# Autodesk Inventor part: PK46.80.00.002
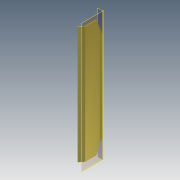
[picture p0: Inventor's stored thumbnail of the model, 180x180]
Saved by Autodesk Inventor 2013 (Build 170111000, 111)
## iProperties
Shininess: 64.0
Length Units: 11269
Angle Units: 11279
Time Units: 11290
Mass Units: 11283
Length Display Precision: 3
Angle Display Precision: 2
Compacted: True
Part Number: PK46.80.00.002
Document SubType Name: Sheet Metal
Created: 2004-12
Material: Steel, Mild
Designer: Salex
Manufacturer: Standard
Standards Organization: Custom
Density: 7.86 g/cm^3
Sheet Metal Rule: Default
Mass: 75176.4 g
Surface Area: 24385.2 cm^2
Volume: 9564.43 cm^3
Density: 0.0
Volumn: 0.0
Area: 0.0
PropertySet Name: Model Information
Control State: 0
Master: False
Checked Out: False
Checked Out Date: 2008-10-15
Last Check In Date: 2008-10-15
Author: Salex
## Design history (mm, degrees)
node "Contour Flange1"
  sketch "Sketch1"
    geometry: L1 (0, 0)-(0, 360); L2 (0, 0)-(-70, -90)
    constraints: 4 end point, 1 vertical, 1 other
    dimensions: "d16" = 70 horizontal distance of L1.start L2.end; "d19" = 360 distance of L1.start L1.end; "d23" = 90 vertical distance of L1.start L2.end
feature "Угловая фаска3" dims "d25" = 300, "d26" = 115, angle "d27" = 45 deg
feature "Угловая фаска4" dims "d28" = 300 (= d25), "d29" = 115 (= d26), angle "d30" = 45 deg
node "РабОсь1"
feature "Сгиб по линии1" dims "d32" = 8 (= BendReliefWidth), "d33" = 4 (= BendReliefDepth), "d34" = 16 (= MinimumRemnant), "d35" = 10 (= BendRadius), "d36" = 50 deg, "d37" = 10 (= BendRadius), "SeamGap" = 0.01, "Thickness" = 8
node "РабПлоскость1"
node "РабПлоскость2"
body "Solid1"
sketch "Эскиз3"
  geometry: L1 (2280, 356.569)-(2580, 241.569) reference; L2 (2280, 356.569)-(300, 356.569) reference; L3 (0, 241.569)-(300, 356.569) reference; L4 (195.652, 316.569)-(2384.348, 316.569)
  constraints: 2 end point, 2 point on line, 1 parallel
  dimensions: "d31" = 40 distance between parallel lines of L2 L4
face "Plate1" dims "d3" = 2580, "d4" = 8 (= BendReliefWidth), "d6" = 16 (= MinimumRemnant), "d8" = 10 (= BendRadius), "d9" = 8, "Thickness" = 8
bend "Bend1" dims "d4" = 8 (= BendReliefWidth), "d5" = 4 (= BendReliefDepth), "d6" = 16 (= MinimumRemnant), "d7" = 10 (= BendRadius), "d8" = 10 (= BendRadius), "d9" = 8, "SeamGap" = 0.01, "Thickness" = 8
other parameters: "BendRadius" = 10, "BendReliefWidth" = 8 (= Thickness), "BendReliefDepth" = 4 (= 0.5 x Thickness), "CornerReliefSize" = 32 (= 4 x Thickness), "MinimumRemnant" = 16 (= 2 x Thickness), "d38" = 90 deg, "d39" = 0, "JacobiRadiusSize" = 8 (= Thickness), "GapSize" = 8 (= Thickness)
